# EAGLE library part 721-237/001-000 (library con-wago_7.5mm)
Serie 721, Stiftleiste (für Leiterplatten) Einlötstift gerade 1 x 1 mm / Series 721, Male header (for PCBs) Straight solder pin 1 x 1 mm Polzahl / Pole No.: 7 Rastermaß / Pitch: 7.5 mm Bemessungsspannung / Rated Voltage: 630 V Nennstrom / Nominal Current: 12 A Lötstiftlänge: / Solder Pin Length: 5 mm Farbe / Color: lichtgrau / light gray Stand: 01.01.2012. Die jeweils aktuellen Daten zu diesem Artikel finden Sie in unserem Produktkatalog, den Sie unter www.wago.com einsehen können. As of: 01/01/2012. Please find the newest data for this article in our product catalogue, which can be viewed under www.wago.com.
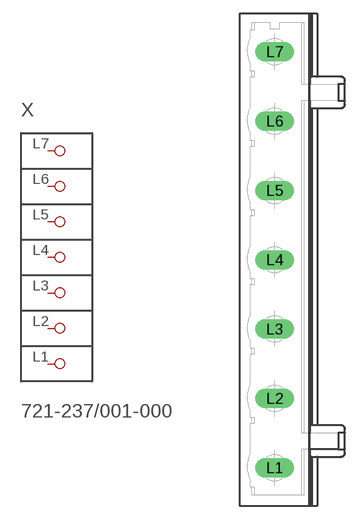
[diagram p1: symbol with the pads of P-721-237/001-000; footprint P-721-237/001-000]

Designator prefix X

## 721-237/001-000  [P-721-237/001-000]
L1  P1
L2  P2
L3  P3
L4  P4
L5  P5
L6  P6
L7  P7

## Footprint P-721-237/001-000 (pad centres in mm)
drill 1.4 long: L1 -1.9,-22.5; L2 -1.9,-15; L3 -1.9,-7.5; L4 -1.9,0; L5 -1.9,7.5; L6 -1.9,15; L7 -1.9,22.5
